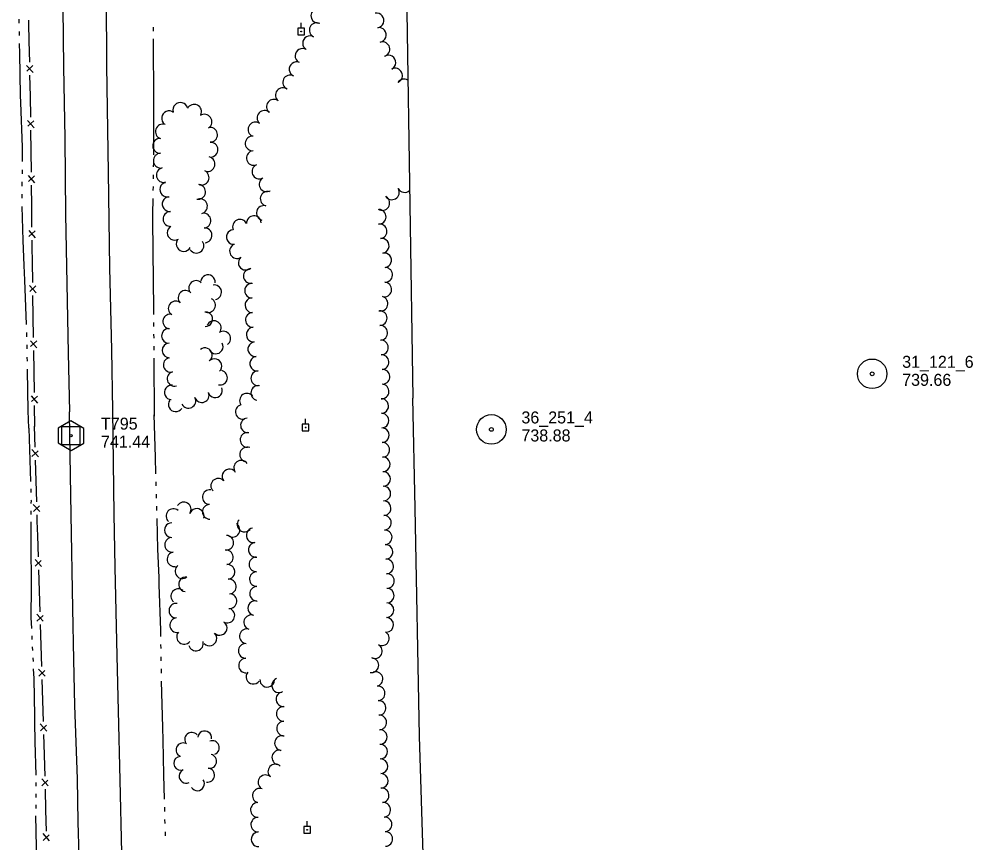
# Model space of a CAD drawing. Extents: x 589250 to 1188077, y 162953 to 363065.
# Drawn here: x 594345.4 to 594821.9, y 167027.2 to 167438.7 of the extents above; entities that cross this region are included whole.
import ezdxf

# ---------------------------------------------------------------- set-up
doc = ezdxf.new("R2010")
doc.units = 0
for name, color, linetype in [('E_FEN_P', 7, 'Continuous'), ('E_LAND_TreeLine_P', 7, 'Continuous'), ('E_MAP_Control', 7, 'Continuous'), ('E_MAP_Limits', 7, 'Continuous'), ('E_MAP_PassPoints', 7, 'Continuous'), ('E_RDWY', 7, 'Continuous'), ('E_UTL_EPowerPole', 7, 'Continuous'), ('E_WTR_FlowLine', 7, 'Continuous')]:
    doc.layers.add(name, color=color, linetype=linetype)

msp = doc.modelspace()

# ---------------------------------------------------------------- linework, layer by layer
at = {"layer": 'E_FEN_P'}
for p, q in [((594350.17, 167438.15), (594350.18, 167436.44)), ((594350.18, 167436.44), (594350.35, 167427.65)), ((594350.35, 167427.65), (594350.55, 167417.15)), ((594349.11, 167415.51), (594352.37, 167411.91)), ((594352.3, 167415.4), (594349.24, 167412.59)), ((594350.68, 167410.65), (594350.88, 167400.15)), ((594350.88, 167400.15), (594351.09, 167389.65)), ((594349.64, 167388.02), (594352.87, 167384.4)), ((594352.83, 167387.89), (594349.74, 167385.1)), ((594351.17, 167383.15), (594351.28, 167372.65)), ((594351.28, 167372.65), (594351.4, 167362.15)), ((594349.94, 167360.52), (594353.17, 167356.9)), ((594353.13, 167360.39), (594350.04, 167357.6)), ((594351.47, 167355.65), (594351.58, 167345.15)), ((594351.58, 167345.15), (594351.7, 167334.65)), ((594350.25, 167333.01), (594353.47, 167329.39)), ((594353.43, 167332.88), (594350.34, 167330.1)), ((594351.77, 167328.15), (594351.81, 167324.53)), ((594351.81, 167324.53), (594351.91, 167317.64)), ((594351.91, 167317.64), (594352.07, 167307.14)), ((594350.63, 167305.51), (594353.87, 167301.9)), ((594353.81, 167305.39), (594350.74, 167302.59)), ((594352.17, 167300.64), (594352.33, 167290.14)), ((594352.33, 167290.14), (594352.48, 167279.64)), ((594351.04, 167278), (594354.28, 167274.39)), ((594354.23, 167277.88), (594351.15, 167275.09)), ((594352.58, 167273.14), (594352.74, 167262.64)), ((594352.74, 167262.64), (594352.9, 167252.14)), ((594351.45, 167250.5), (594354.69, 167246.89)), ((594354.64, 167250.38), (594351.56, 167247.58)), ((594352.99, 167245.64), (594353.15, 167235.14)), ((594353.44, 167224.88), (594353.15, 167235.35)), ((594355.04, 167220.06), (594351.76, 167223.61)), ((594351.86, 167220.13), (594354.89, 167222.96)), ((594353.91, 167207.94), (594353.62, 167218.4)), ((594354.2, 167197.48), (594353.91, 167207.94)), ((594355.8, 167192.65), (594352.53, 167196.21)), ((594352.63, 167192.73), (594355.66, 167195.56)), ((594354.47, 167187.83), (594354.38, 167191)), ((594354.7, 167180.53), (594354.47, 167187.83)), ((594355.04, 167170.07), (594354.7, 167180.53)), ((594356.66, 167165.25), (594353.37, 167168.8)), ((594353.48, 167165.32), (594356.5, 167168.16)), ((594355.57, 167153.13), (594355.24, 167163.59)), ((594355.9, 167142.67), (594355.57, 167153.13)), ((594357.52, 167137.85), (594354.23, 167141.39)), ((594354.34, 167137.91), (594357.37, 167140.76)), ((594356.44, 167125.73), (594356.11, 167136.19)), ((594356.77, 167115.27), (594356.44, 167125.73)), ((594358.39, 167110.45), (594355.1, 167113.99)), ((594355.21, 167110.51), (594358.23, 167113.35)), ((594357.31, 167098.33), (594356.98, 167108.79)), ((594357.64, 167087.86), (594357.31, 167098.33)), ((594359.26, 167083.04), (594355.97, 167086.59)), ((594356.08, 167083.11), (594359.1, 167085.95)), ((594358, 167076.47), (594357.85, 167081.39)), ((594358.14, 167070.92), (594358, 167076.47)), ((594358.39, 167060.46), (594358.14, 167070.92)), ((594359.97, 167055.63), (594356.71, 167059.19)), ((594356.8, 167055.72), (594359.84, 167058.53)), ((594358.8, 167043.51), (594358.55, 167053.98)), ((594359.05, 167033.05), (594358.8, 167043.51)), ((594360.64, 167028.22), (594357.38, 167031.79)), ((594357.46, 167028.31), (594360.5, 167031.13))]:
    msp.add_line(p, q, dxfattribs=at)
at = {"layer": 'E_LAND_TreeLine_P'}
for centre, radius, start, end in [((594494.82, 167440.33), 3.66, 89.3299, 269.3299), ((594523.97, 167437.96), 3.66, 279.6336, 99.6336), ((594494.07, 167433.12), 3.66, 63.3066, 243.3066), ((594525.2, 167430.74), 3.66, 279.6336, 99.6336), ((594490.75, 167426.59), 3.66, 58.8437, 238.8437), ((594526.95, 167423.63), 3.66, 284.7226, 104.7226), ((594486.96, 167420.32), 3.66, 58.8437, 238.8437), ((594484.01, 167413.62), 3.66, 66.6874, 246.6874), ((594529.88, 167416.96), 3.66, 297.9163, 117.9163), ((594533.24, 167410.45), 3.66, 296.2028, 116.2028), ((594480.82, 167407.02), 3.66, 64.0818, 244.0818), ((594537.76, 167405.02), 3.66, 58.7627, 146.9486), ((594477.15, 167400.69), 3.66, 52.2574, 232.2574), ((594472.64, 167394.92), 3.66, 51.5457, 231.5457), ((594420.37, 167389.11), 3.7, 52.4237, 232.4237), ((594425.99, 167393.3), 3.7, 15.2424, 195.2424), ((594432.86, 167392.37), 3.7, 334.3006, 154.3006), ((594467.98, 167389.32), 3.66, 47.2753, 227.2753), ((594438.02, 167387.4), 3.7, 304.3579, 124.3579), ((594417.26, 167382.49), 3.7, 71.0281, 251.0281), ((594440.83, 167380.85), 3.7, 271.7049, 91.7049), ((594463.51, 167383.53), 3.66, 54.8224, 234.8224), ((594415.86, 167375.35), 3.7, 92.4745, 272.4745), ((594462.04, 167376.55), 3.66, 85.8237, 265.8237), ((594441.05, 167373.46), 3.7, 271.7049, 91.7049), ((594416.18, 167367.96), 3.7, 92.4745, 272.4745), ((594439.58, 167366.24), 3.7, 256.7977, 76.7977), ((594462.68, 167369.27), 3.66, 96.1149, 276.1149), ((594417.74, 167360.73), 3.7, 102.3191, 282.3191), ((594465.44, 167362.51), 3.66, 113.8477, 293.8477), ((594436.6, 167359.48), 3.7, 245.1631, 65.1631), ((594469.01, 167356.11), 3.66, 119.4826, 299.4826), ((594419.45, 167353.54), 3.7, 103.6352, 283.6352), ((594434.83, 167352.37), 3.7, 261.0464, 81.0464), ((594420.63, 167346.25), 3.7, 96.749, 276.749), ((594469.57, 167348.9), 3.66, 74.652, 254.652), ((594526.84, 167346.78), 3.66, 236.6878, 56.6878), ((594531.65, 167352.09), 3.66, 210.9049, 30.9049), ((594537.99, 167355.76), 3.66, 208.4348, 313.7319), ((594435.78, 167345.18), 3.7, 285.4702, 105.4702), ((594467.63, 167341.83), 3.66, 74.652, 254.652), ((594421.05, 167338.81), 3.7, 92.9278, 272.9278), ((594437.53, 167338.01), 3.7, 274.1784, 94.1784), ((594462.72, 167336.76), 3.66, 3.1411, 183.1411), ((594525.08, 167339.93), 3.66, 267.4397, 87.4397), ((594423.14, 167331.93), 3.7, 119.9954, 299.9954), ((594455.75, 167334.96), 3.66, 24.739, 204.739), ((594525.5, 167332.65), 3.66, 278.2625, 98.2625), ((594438.07, 167330.64), 3.7, 274.1784, 94.1784), ((594452.71, 167329.8), 3.66, 95.2517, 275.2517), ((594427.64, 167326.34), 3.7, 151.0548, 331.0548), ((594434, 167325.52), 3.7, 213.6709, 33.6709), ((594454.25, 167322.78), 3.66, 120.131, 300.131), ((594526.56, 167325.4), 3.66, 279.4358, 99.4358), ((594527.76, 167318.17), 3.66, 279.4358, 99.4358), ((594458.66, 167316.99), 3.66, 133.146, 313.146), ((594461.16, 167310.31), 3.66, 102.8561, 282.8561), ((594528.3, 167310.91), 3.66, 266.6178, 86.6178), ((594433.81, 167304.38), 3.63, 43.6882, 223.6882), ((594439.77, 167307.3), 3.63, 353.6552, 173.6552), ((594461.78, 167303.04), 3.66, 91.3512, 271.3512), ((594527.87, 167303.59), 3.66, 266.6178, 86.6178), ((594428.5, 167299.44), 3.63, 42.2879, 222.2879), ((594442.9, 167302.22), 3.63, 279.1803, 99.1803), ((594423.6, 167294.16), 3.63, 57.3548, 237.3548), ((594439.87, 167295.73), 3.63, 242.4525, 62.4525), ((594461.96, 167295.72), 3.66, 91.3512, 271.3512), ((594526, 167296.51), 3.66, 254.8912, 74.8912), ((594438.46, 167288.79), 3.63, 268.5988, 88.5988), ((594525.58, 167289.26), 3.66, 271.3512, 91.3512), ((594420.87, 167287.64), 3.63, 84.3785, 264.3785), ((594442.74, 167284.33), 3.63, 335.5639, 155.5639), ((594462.19, 167288.39), 3.66, 92.3223, 272.3223), ((594420.24, 167280.41), 3.63, 91.9242, 271.9242), ((594447.44, 167279.08), 3.63, 304.0235, 124.0235), ((594462.59, 167281.08), 3.66, 94.396, 274.396), ((594525.82, 167281.94), 3.66, 273.1136, 93.1136), ((594526.2, 167274.62), 3.66, 271.8817, 91.8817), ((594420.48, 167273.16), 3.63, 91.9242, 271.9242), ((594438.29, 167270.81), 3.63, 308.9198, 128.9198), ((594443.7, 167275.11), 3.63, 206.6709, 26.6709), ((594463.37, 167273.8), 3.66, 97.6109, 277.6109), ((594421.12, 167265.97), 3.63, 105.3057, 285.3057), ((594443.02, 167265.32), 3.63, 315.166, 135.166), ((594464.34, 167266.54), 3.66, 97.6109, 277.6109), ((594526.48, 167267.3), 3.66, 273.9736, 93.9736), ((594526.98, 167259.99), 3.66, 273.9736, 93.9736), ((594423.04, 167258.97), 3.63, 105.3057, 285.3057), ((594445.84, 167259.53), 3.63, 257.2054, 77.2054), ((594464.9, 167259.24), 3.66, 91.1948, 271.1948), ((594421.7, 167252.21), 3.63, 85.297, 265.297), ((594443.33, 167253.23), 3.63, 201.2676, 21.2676), ((594464.89, 167251.93), 3.66, 79.8848, 259.8848), ((594526.52, 167252.68), 3.66, 265.9035, 85.9035), ((594430.04, 167247.94), 3.63, 206.629, 26.629), ((594436.7, 167250.78), 3.63, 201.5979, 21.5979), ((594459.23, 167248.05), 3.66, 34.4697, 214.4697), ((594423.66, 167246.19), 3.63, 145.1931, 325.1931), ((594457.17, 167242.46), 3.66, 105.6651, 285.6651), ((594526.34, 167245.39), 3.64, 271.1948, 91.1948), ((594526.49, 167238.1), 3.64, 271.1948, 91.1948), ((594459.74, 167235.74), 3.66, 96.9054, 276.9054), ((594459.51, 167228.44), 3.66, 91.1948, 271.1948), ((594526.64, 167230.81), 3.64, 271.1948, 91.1948), ((594526.89, 167223.52), 3.64, 272.4137, 92.4137), ((594459.32, 167221.17), 3.66, 69.2037, 249.2037), ((594456.39, 167214.57), 3.66, 36.0973, 216.0973), ((594527.08, 167216.24), 3.64, 271.1948, 91.1948), ((594450.49, 167210.22), 3.66, 38.4987, 218.4987), ((594527.23, 167208.95), 3.64, 271.1948, 91.1948), ((594444.86, 167205.55), 3.66, 45.41, 225.41), ((594440.68, 167199.86), 3.66, 82.664, 262.664), ((594527.38, 167201.66), 3.64, 271.1948, 91.1948), ((594427.64, 167193.72), 3.66, 328.1709, 148.1709), ((594527.53, 167194.37), 3.64, 271.1948, 91.1948), ((594422.52, 167190.42), 3.66, 49.3746, 229.3746), ((594434.15, 167190.47), 3.66, 342.7598, 162.7598), ((594440.68, 167192.55), 3.66, 91.1948, 271.1948), ((594458.03, 167186.18), 3.66, 138.6843, 318.6843), ((594527.72, 167187.09), 3.64, 272.8008, 92.8008), ((594421.69, 167183.4), 3.66, 89.9494, 269.9494), ((594452.01, 167183.58), 3.66, 238.0834, 58.0834), ((594462.58, 167180.82), 3.66, 98.4191, 278.4191), ((594528.08, 167179.81), 3.64, 272.8008, 92.8008), ((594421.86, 167176.08), 3.66, 99.2119, 279.2119), ((594448.94, 167177.11), 3.66, 267.5034, 87.5034), ((594448.72, 167169.8), 3.66, 276.4572, 96.4572), ((594463.65, 167173.57), 3.66, 98.4191, 278.4191), ((594528.44, 167172.53), 3.64, 273.0727, 93.0727), ((594423.03, 167168.85), 3.66, 99.2119, 279.2119), ((594463.95, 167166.26), 3.66, 91.751, 271.751), ((594528.83, 167165.25), 3.64, 273.0727, 93.0727), ((594427.01, 167162.86), 3.66, 128.3795, 308.3795), ((594449.54, 167162.52), 3.66, 276.4572, 96.4572), ((594428.81, 167156.35), 3.66, 82.4486, 262.4486), ((594450.24, 167155.22), 3.66, 275.0089, 95.0089), ((594464.17, 167158.93), 3.66, 91.1948, 271.1948), ((594529.22, 167157.97), 3.64, 273.0727, 93.0727), ((594424.92, 167150.39), 3.66, 49.7711, 229.7711), ((594464.33, 167151.61), 3.66, 91.1948, 271.1948), ((594529.11, 167150.68), 3.64, 269.0131, 89.0131), ((594450.51, 167147.92), 3.66, 265.7545, 85.7545), ((594423.96, 167143.19), 3.66, 84.1783, 264.1783), ((594463.38, 167144.41), 3.66, 76.0937, 256.0937), ((594528.99, 167143.39), 3.64, 268.9636, 88.9636), ((594449.46, 167140.77), 3.66, 239.3959, 59.3959), ((594461.36, 167137.37), 3.66, 70.5359, 250.5359), ((594528.86, 167136.1), 3.64, 268.9636, 88.9636), ((594424.39, 167135.91), 3.66, 96.3892, 276.3892), ((594445.62, 167134.56), 3.66, 225.6161, 45.6161), ((594427.82, 167130.07), 3.66, 141.1885, 321.1885), ((594440.49, 167129.32), 3.66, 225.6161, 45.6161), ((594459.24, 167130.39), 3.66, 84.5404, 264.5404), ((594526.65, 167129.35), 3.64, 241.7411, 61.7411), ((594433.8, 167126.76), 3.66, 194.9764, 14.9764), ((594458.62, 167123.1), 3.66, 91.1948, 271.1948), ((594523.2, 167122.93), 3.64, 241.7411, 61.7411), ((594458.77, 167115.77), 3.66, 91.1948, 271.1948), ((594521.46, 167115.9), 3.64, 259.0233, 79.0233), ((594462.47, 167110.19), 3.66, 141.0939, 321.0939), ((594523.49, 167109.03), 3.64, 290.4848, 110.4848), ((594469.35, 167108.67), 3.66, 177.1092, 357.1092), ((594475.35, 167105.88), 3.66, 111.7508, 291.7508), ((594477.42, 167098.91), 3.66, 95.7687, 275.7687), ((594524.57, 167101.89), 3.64, 273.5085, 93.5085), ((594525.02, 167094.61), 3.64, 273.5085, 93.5085), ((594477.65, 167091.59), 3.66, 91.1948, 271.1948), ((594477.8, 167084.27), 3.66, 91.1948, 271.1948), ((594525.36, 167087.33), 3.64, 272.5587, 92.5587), ((594438.11, 167079.58), 3.49, 353.3795, 173.3795), ((594525.63, 167080.05), 3.64, 271.1948, 91.1948), ((594431.65, 167078.85), 3.49, 40.0482, 220.0482), ((594441.93, 167074.71), 3.49, 291.9203, 111.9203), ((594476.74, 167077.02), 3.66, 81.1868, 261.1868), ((594427.33, 167073.6), 3.49, 66.3311, 246.3311), ((594475.4, 167069.83), 3.66, 76.3683, 256.3683), ((594525.78, 167072.76), 3.64, 271.1948, 91.1948), ((594426.21, 167066.91), 3.49, 92.9305, 272.9305), ((594440.58, 167067.92), 3.49, 257.4132, 77.4132), ((594525.98, 167065.47), 3.64, 271.5954, 91.5954), ((594428.85, 167060.5), 3.49, 114.5503, 294.5503), ((594439.55, 167061.03), 3.49, 261.9015, 81.9015), ((594473.41, 167062.85), 3.66, 47.4137, 227.4137), ((594468.45, 167057.45), 3.66, 47.4137, 227.4137), ((594526.18, 167058.19), 3.64, 271.5954, 91.5954), ((594434.49, 167056.74), 3.49, 212.8023, 32.8023), ((594465.66, 167050.75), 3.66, 70.4487, 250.4487), ((594526.55, 167050.91), 3.64, 276.4366, 96.4366), ((594464.7, 167043.61), 3.66, 91.1948, 271.1948), ((594527.36, 167043.67), 3.64, 276.4366, 96.4366), ((594464.85, 167036.28), 3.66, 91.1948, 271.1948), ((594528.05, 167036.42), 3.64, 272.4401, 92.4401), ((594465.09, 167028.96), 3.66, 91.9021, 271.9021), ((594528.36, 167029.13), 3.64, 272.4401, 92.4401)]:
    msp.add_arc(centre, radius, start, end, dxfattribs=at)
at = {"layer": 'E_MAP_Control'}
for p, q in [((594366.83, 167226.08), (594366.83, 167235.08)), ((594366.83, 167235.08), (594375.83, 167235.08)), ((594366.83, 167226.08), (594366.83, 167235.08)), ((594366.83, 167235.08), (594375.83, 167235.08)), ((594375.83, 167235.08), (594375.83, 167226.08)), ((594375.83, 167235.08), (594375.83, 167226.08)), ((594375.83, 167226.08), (594366.83, 167226.08)), ((594375.83, 167226.08), (594366.83, 167226.08))]:
    msp.add_line(p, q, dxfattribs=at)
msp.add_lwpolyline([(594364.92, 167234.34), (594364.92, 167226.95), (594371.38, 167223.22), (594377.77, 167226.89), (594377.77, 167234.21), (594371.25, 167237.94)], close=True, dxfattribs=at)
msp.add_lwpolyline([(594364.92, 167234.34), (594364.92, 167226.95), (594371.38, 167223.22), (594377.77, 167226.89), (594377.77, 167234.21), (594371.25, 167237.94)], close=True, dxfattribs=at)
msp.add_circle((594371.33, 167230.58), 0.546, dxfattribs=at)
msp.add_circle((594371.33, 167230.58), 0.546, dxfattribs=at)
at = {"layer": 'E_MAP_Limits'}
for p, q in [((594539.12, 167442.44), (594542.15, 167249.29)), ((594543.2, 167194.33), (594542.15, 167249.29)), ((594545.51, 167080.52), (594543.2, 167194.33)), ((594551.12, 166891.35), (594545.51, 167080.52))]:
    msp.add_line(p, q, dxfattribs=at)
at = {"layer": 'E_MAP_PassPoints'}
for centre, radius in [((594771.55, 167261.49), 7.38), ((594771.55, 167261.49), 7.38), ((594771.55, 167261.49), 0.945), ((594771.55, 167261.49), 0.945), ((594581.35, 167233.7), 7.38), ((594581.35, 167233.7), 7.38), ((594581.35, 167233.7), 0.945), ((594581.35, 167233.7), 0.945)]:
    msp.add_circle(centre, radius, dxfattribs=at)
at = {"layer": 'E_RDWY'}
for p, q in [((594389.28, 167415.36), (594389.09, 167457.46)), ((594367.35, 167444.34), (594367.65, 167414.67)), ((594367.65, 167414.67), (594368.22, 167379.2)), ((594390.14, 167362.14), (594389.28, 167415.36)), ((594368.22, 167379.2), (594368.65, 167341.11)), ((594390.8, 167314.37), (594390.14, 167362.14)), ((594368.65, 167341.11), (594369.95, 167271.97)), ((594391.77, 167273.49), (594390.8, 167314.37)), ((594392.17, 167243.21), (594391.77, 167273.49)), ((594369.95, 167271.97), (594370.59, 167242.56)), ((594370.84, 167230.63), (594370.59, 167242.56)), ((594392.98, 167191.33), (594392.17, 167243.21)), ((594371.39, 167191.22), (594370.84, 167230.63)), ((594372.24, 167144.17), (594371.39, 167191.22)), ((594393.46, 167164.93), (594392.98, 167191.33)), ((594394.39, 167120.69), (594393.46, 167164.93)), ((594372.84, 167118.57), (594372.24, 167144.17)), ((594395.11, 167093.15), (594394.39, 167120.69)), ((594373.32, 167095.85), (594372.84, 167118.57)), ((594374.55, 167059.13), (594373.32, 167095.85)), ((594395.97, 167058.57), (594395.11, 167093.15)), ((594375, 167037.49), (594374.55, 167059.13)), ((594396.79, 167022.18), (594395.97, 167058.57)), ((594375.35, 167020.8), (594375, 167037.49))]:
    msp.add_line(p, q, dxfattribs=at)
at = {"layer": 'E_UTL_EPowerPole'}
for points in [[(594486.28, 167434.1), (594486.28, 167436.75)], [(594487.95, 167434.1), (594484.6, 167434.1)], [(594484.6, 167434.1), (594484.6, 167430.75)], [(594484.6, 167430.75), (594487.95, 167430.75)], [(594487.95, 167430.75), (594487.95, 167434.1)], [(594490.22, 167236.37), (594486.87, 167236.37)], [(594486.87, 167236.37), (594486.87, 167233.01)], [(594488.54, 167236.37), (594488.54, 167239.01)], [(594490.22, 167233.01), (594490.22, 167236.37)], [(594486.87, 167233.01), (594490.22, 167233.01)], [(594490.98, 167035.34), (594487.63, 167035.34)], [(594487.63, 167035.34), (594487.63, 167031.99)], [(594489.3, 167035.34), (594489.3, 167037.99)], [(594490.98, 167031.99), (594490.98, 167035.34)], [(594487.63, 167031.99), (594490.98, 167031.99)]]:
    msp.add_lwpolyline(points, dxfattribs=at)
for centre in [(594486.31, 167432.43), (594488.57, 167234.69), (594489.33, 167033.67)]:
    msp.add_circle(centre, 0.217, dxfattribs=at)
at = {"layer": 'E_WTR_FlowLine'}
for p, q in [((594345.46, 167436.61), (594345.41, 167438.64)), ((594345.6, 167430.51), (594345.56, 167432.54)), ((594412.37, 167434.7), (594412.36, 167432.7)), ((594345.82, 167421.39), (594345.7, 167426.44)), ((594412.34, 167428.72), (594412.33, 167426.19)), ((594412.33, 167426.19), (594412.48, 167399.81)), ((594346.11, 167400.41), (594345.82, 167421.39)), ((594346.26, 167396.95), (594346.11, 167400.41)), ((594412.48, 167399.81), (594412.49, 167396.45)), ((594347.19, 167374.64), (594346.26, 167396.95)), ((594412.49, 167396.45), (594412.55, 167371.59)), ((594347.11, 167367.47), (594347.19, 167374.64)), ((594412.55, 167371.59), (594412.54, 167370.91)), ((594412.48, 167366.92), (594412.45, 167364.93)), ((594347.05, 167361.37), (594347.07, 167363.4)), ((594412.4, 167360.94), (594412.37, 167358.95)), ((594346.98, 167355.26), (594347, 167357.3)), ((594412.32, 167354.96), (594412.29, 167352.97)), ((594346.91, 167349.16), (594346.94, 167351.19)), ((594347.48, 167328.13), (594346.97, 167345.09)), ((594412.23, 167348.98), (594412.13, 167341.24)), ((594412.13, 167341.24), (594412.3, 167320.08)), ((594347.95, 167315.61), (594347.48, 167328.13)), ((594412.3, 167320.08), (594412.37, 167310.9)), ((594348.22, 167308.23), (594347.95, 167315.61)), ((594349.2, 167286.14), (594348.22, 167308.23)), ((594412.37, 167310.9), (594412.55, 167291.17)), ((594412.58, 167287.19), (594412.6, 167285.19)), ((594349.32, 167280.03), (594349.29, 167282.07)), ((594412.64, 167281.21), (594412.66, 167279.21)), ((594349.43, 167273.93), (594349.39, 167275.97)), ((594412.69, 167275.22), (594412.7, 167274.55)), ((594412.7, 167274.55), (594412.71, 167273.23)), ((594349.54, 167267.83), (594349.5, 167269.86)), ((594412.73, 167269.24), (594412.92, 167240.34)), ((594349.61, 167263.36), (594349.61, 167263.76)), ((594349.89, 167242.98), (594349.61, 167263.36)), ((594350.21, 167234.27), (594349.89, 167242.98)), ((594413.54, 167219.9), (594412.9, 167241.01)), ((594350.21, 167234.27), (594351.15, 167207.68)), ((594413.77, 167211.55), (594413.54, 167219.9)), ((594413.94, 167205.46), (594413.88, 167207.49)), ((594351.25, 167204.01), (594351.28, 167202.18)), ((594351.36, 167198.51), (594351.37, 167198.22)), ((594351.37, 167198.22), (594351.36, 167196.67)), ((594414.08, 167200.6), (594414.05, 167201.39)), ((594414.11, 167199.36), (594414.08, 167200.6)), ((594351.34, 167193), (594351.34, 167191.17)), ((594414.26, 167193.27), (594414.21, 167195.3)), ((594351.32, 167187.5), (594351.25, 167171.6)), ((594414.77, 167173.93), (594414.37, 167189.21)), ((594415.33, 167159.75), (594414.77, 167173.93)), ((594351.25, 167171.6), (594351.39, 167160.89)), ((594351.39, 167160.89), (594351.47, 167154.84)), ((594415.47, 167156.04), (594415.33, 167159.75)), ((594351.47, 167154.84), (594351.24, 167139.82)), ((594416.15, 167133.46), (594415.47, 167156.04)), ((594351.24, 167139.82), (594351.54, 167134.29)), ((594351.74, 167130.63), (594351.83, 167128.8)), ((594416.2, 167130.3), (594416.15, 167133.46)), ((594416.31, 167124.2), (594416.28, 167126.23)), ((594352.03, 167125.13), (594352.12, 167123.34)), ((594352.12, 167123.34), (594352.13, 167123.3)), ((594352.29, 167119.63), (594352.37, 167117.8)), ((594416.42, 167118.11), (594416.39, 167120.14)), ((594352.53, 167114.13), (594352.75, 167109.21)), ((594416.54, 167112.01), (594416.5, 167114.04)), ((594352.75, 167109.21), (594353.15, 167090.44)), ((594417.16, 167084.81), (594416.61, 167107.95)), ((594353.15, 167090.44), (594353.16, 167087.53)), ((594353.16, 167087.53), (594353.21, 167077.71)), ((594417.31, 167078.49), (594417.16, 167084.81)), ((594417.72, 167061.22), (594417.31, 167078.49)), ((594353.21, 167077.71), (594353.73, 167060.94)), ((594418.04, 167049.03), (594417.72, 167061.22)), ((594353.82, 167057.27), (594353.8, 167055.43)), ((594353.77, 167051.76), (594353.75, 167049.93)), ((594353.71, 167046.26), (594353.7, 167044.42)), ((594418.19, 167042.93), (594418.14, 167044.96)), ((594353.69, 167040.75), (594353.74, 167033.13)), ((594418.35, 167036.84), (594418.3, 167038.87)), ((594353.74, 167033.13), (594354.1, 167015.57)), ((594418.57, 167030.74), (594418.48, 167032.77))]:
    msp.add_line(p, q, dxfattribs=at)

# ---------------------------------------------------------------- texts
at = {"layer": 'E_MAP_Control'}
for s, p in [('T795', (594386.34, 167233.58)), ('T795', (594386.34, 167233.58)), ('741.44', (594386.34, 167224.58)), ('741.44', (594386.34, 167224.58))]:
    msp.add_text(s, height=6, dxfattribs=at).set_placement(p)
at = {"layer": 'E_MAP_PassPoints'}
for s, p in [('31_121_6', (594786.55, 167264.47)), ('31_121_6', (594786.55, 167264.47)), ('739.66', (594786.55, 167255.47)), ('739.66', (594786.55, 167255.47)), ('36_251_4', (594596.35, 167236.68)), ('36_251_4', (594596.35, 167236.68)), ('738.88', (594596.35, 167227.68)), ('738.88', (594596.35, 167227.68))]:
    msp.add_text(s, height=6, dxfattribs=at).set_placement(p)

doc.saveas('drawing.dxf')
